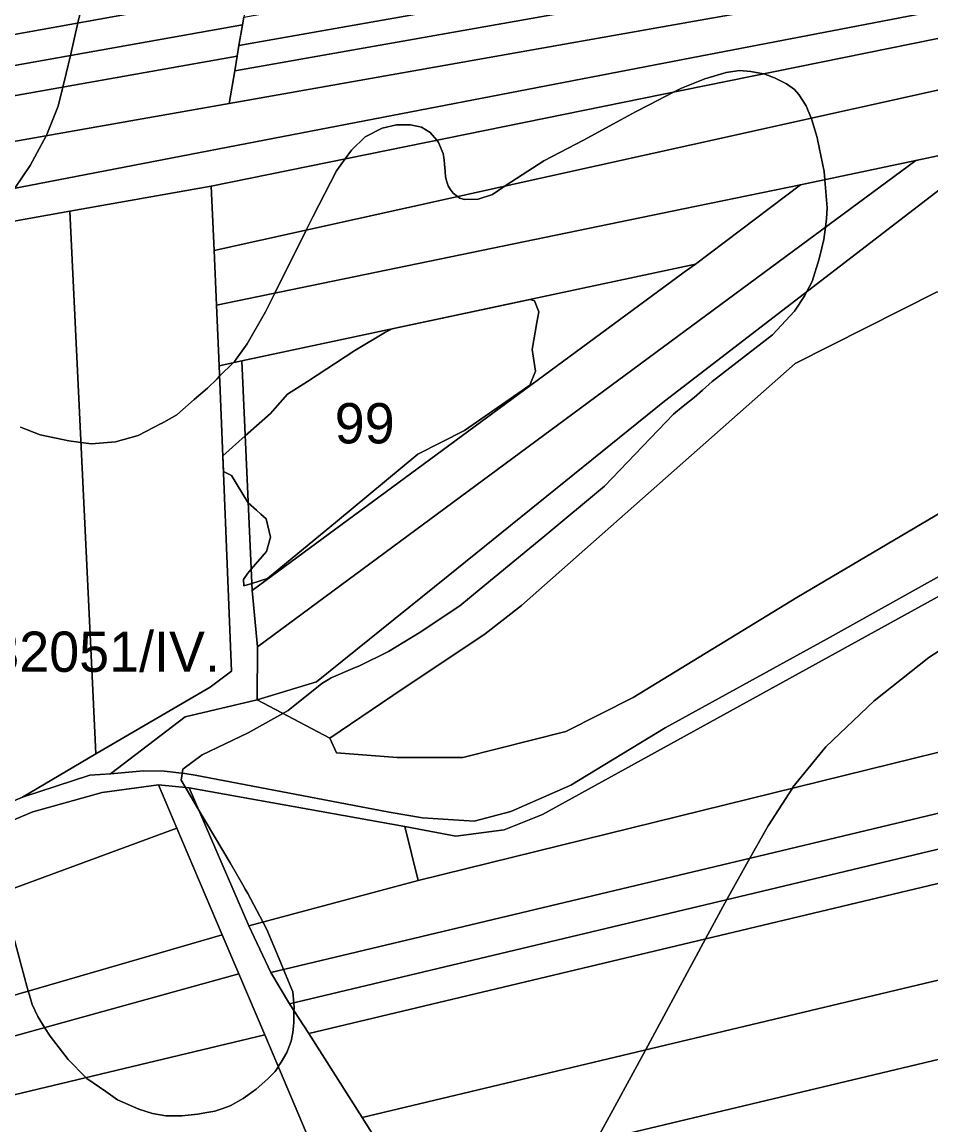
# Model space of a CAD drawing. Extents: x -521939 to -516426, y -1197857 to -1189551.
# Drawn here: x -521390.7 to -521052.2, y -1191196.8 to -1190786 of the extents above; entities that cross this region are included whole.
import ezdxf

# ---------------------------------------------------------------- set-up
doc = ezdxf.new("R2010")
doc.units = 0
for name, color, linetype in [('95560013', 7, 'Continuous'), ('95610013', 7, 'Continuous'), ('95630013', 7, 'Continuous'), ('95640013', 7, 'Continuous'), ('95660013', 7, 'Continuous')]:
    doc.layers.add(name, color=color, linetype=linetype)

msp = doc.modelspace()

# ---------------------------------------------------------------- linework, layer by layer
at = {"layer": '95560013'}
for points in [[(-521290.17, -1190674.88), (-521293.24, -1190693.91), (-521296.33, -1190712.88), (-521297.51, -1190719.97), (-521298.87, -1190728.16), (-521300.83, -1190740.08), (-521302.74, -1190751.74), (-521304.64, -1190763.28), (-521306.54, -1190774.85), (-521450.36, -1190800.76), (-521627.54, -1190832.68), (-521603.17, -1190799.85), (-521437.14, -1190733.56)], [(-521308.13, -1190784.21), (-521129.72, -1190752.09), (-520951.31, -1190719.97), (-520853.44, -1190702.35), (-520853.63, -1190713.88), (-520965.54, -1190733.72), (-521143.84, -1190765.33), (-521309.9, -1190794.77), (-521308.62, -1190787.06)], [(-521310.55, -1190798.66), (-521309.9, -1190794.77), (-521143.84, -1190765.33), (-520965.54, -1190733.72), (-520853.63, -1190713.88), (-520853.79, -1190723.11), (-520956.84, -1190741.35), (-521130.85, -1190772.15), (-521311.47, -1190804.12)], [(-520853.79, -1190723.11), (-520853.87, -1190735.1), (-520958.48, -1190753.58), (-521136, -1190784.94), (-521313.52, -1190816.3), (-521311.47, -1190804.12), (-521130.85, -1190772.15), (-520956.84, -1190741.35)], [(-521313.52, -1190816.3), (-521136, -1190784.94), (-520958.48, -1190753.58), (-520853.87, -1190735.1), (-520853.81, -1190743.83), (-520959.05, -1190764.12), (-521138.15, -1190798.65), (-521317.25, -1190833.18), (-521501.29, -1190868.66), (-521677.29, -1190902.59), (-521660.16, -1190877.52), (-521482.65, -1190846.17)], [(-521681.39, -1190911.18), (-521677.29, -1190902.59), (-521501.29, -1190868.66), (-521317.25, -1190833.18), (-521138.15, -1190798.65), (-520959.05, -1190764.12), (-520853.81, -1190743.83), (-520853.6, -1190752.22), (-520963.96, -1190774.66), (-521145.09, -1190811.49), (-521320.22, -1190847.1), (-521372.85, -1190856.47), (-521425.01, -1190865.8), (-521453.93, -1190870.89), (-521460.01, -1190871.96), (-521483.31, -1190876.02), (-521504.24, -1190879.82), (-521526.13, -1190883.61), (-521548.65, -1190887.54)], [(-520853.6, -1190752.22), (-520853.48, -1190767.88), (-520962.56, -1190792.05), (-521140.87, -1190831.56), (-521319.18, -1190871.07), (-521320.22, -1190847.1), (-521145.09, -1190811.49), (-520963.96, -1190774.66)], [(-521636.8, -1190845.39), (-521627.54, -1190832.68), (-521450.36, -1190800.76), (-521306.54, -1190774.85), (-521306.91, -1190777.02), (-521308.13, -1190784.21), (-521308.62, -1190787.06), (-521459.01, -1190813.79)], [(-521308.62, -1190787.06), (-521309.9, -1190794.77), (-521310.55, -1190798.66), (-521470.11, -1190827.02), (-521646.38, -1190858.35), (-521636.8, -1190845.39), (-521459.01, -1190813.79)], [(-521646.38, -1190858.35), (-521470.11, -1190827.02), (-521310.55, -1190798.66), (-521311.47, -1190804.12), (-521313.52, -1190816.3), (-521482.65, -1190846.17), (-521660.16, -1190877.52)], [(-521204.73, -1191003.3), (-521102.75, -1190913.16), (-521050.15, -1190886.58), (-521012.31, -1190879.41), (-520849.49, -1190848.58), (-520847.98, -1190871.46), (-520845.07, -1190897.78), (-520896.6, -1190901.88), (-520958.97, -1190920.92), (-521001.86, -1190941.06), (-521102.12, -1191000.34), (-521163.1, -1191037.51), (-521188.22, -1191050.28), (-521226.57, -1191059.93), (-521251.03, -1191059.96), (-521273.53, -1191058.18), (-521276.05, -1191052.73), (-521252.59, -1191036.79), (-521218.27, -1191013.84)], [(-521248.14, -1191085.64), (-521229.14, -1191089.2), (-521211.09, -1191086.92), (-521196.9, -1191081.18), (-521042.5, -1190996.08), (-520867.54, -1190954.4), (-520838.45, -1190947.47), (-520829.51, -1191003.76), (-520890.59, -1191018.81), (-521066.89, -1191062.25), (-521243.19, -1191105.69)], [(-520829.51, -1191003.76), (-520825.08, -1191027.11), (-520948.1, -1191056.48), (-521121.97, -1191097.99), (-521298.06, -1191140.03), (-521306.22, -1191122.56), (-521243.19, -1191105.69), (-521066.89, -1191062.25), (-520890.59, -1191018.81)], [(-520825.08, -1191027.11), (-520822.58, -1191039.85), (-520945.68, -1191069.25), (-521118.02, -1191110.41), (-521291.03, -1191151.73), (-521298.06, -1191140.03), (-521121.97, -1191097.99), (-520948.1, -1191056.48)], [(-520945.68, -1191069.25), (-520822.58, -1191039.85), (-520820.01, -1191052.05), (-520940.27, -1191080.75), (-521112.07, -1191121.75), (-521283.87, -1191162.75), (-521291.03, -1191151.73), (-521118.02, -1191110.41)], [(-520820.01, -1191052.05), (-520812.23, -1191086.24), (-520915.1, -1191110.79), (-521089.12, -1191152.32), (-521264.02, -1191194.06), (-521283.87, -1191162.75), (-521112.07, -1191121.75), (-520940.27, -1191080.75)], [(-521339.87, -1191070.1), (-521333.03, -1191086.18), (-521492.1, -1191144.87), (-521665.86, -1191208.98), (-521668.23, -1191202.31), (-521666.02, -1191197.62), (-521498.24, -1191127.07), (-521386.68, -1191080.16), (-521360.86, -1191072.9)], [(-521243.19, -1191105.69), (-521306.22, -1191122.56), (-521328.5, -1191071.27), (-521248.14, -1191085.64)], [(-521333.03, -1191086.18), (-521316.14, -1191125.96), (-521487.7, -1191175.74), (-521659.26, -1191225.52), (-521665.86, -1191208.98), (-521492.1, -1191144.87)], [(-520812.23, -1191086.24), (-520805.2, -1191114.16), (-520903.8, -1191137.67), (-521078.73, -1191179.38), (-521253.66, -1191221.09), (-521257.44, -1191204.41), (-521264.02, -1191194.06), (-521089.12, -1191152.32), (-520915.1, -1191110.79)], [(-520805.2, -1191114.16), (-520797.61, -1191144.17), (-520897.63, -1191168.05), (-521072.33, -1191209.76), (-521247.03, -1191251.47), (-521253.66, -1191221.09), (-521078.73, -1191179.38), (-520903.8, -1191137.67)], [(-521659.26, -1191225.52), (-521487.7, -1191175.74), (-521316.14, -1191125.96), (-521309.96, -1191140.46), (-521476.8, -1191186.64), (-521654.37, -1191235.79)], [(-521300.29, -1191163.2), (-521649.4, -1191246.83), (-521654.37, -1191235.79), (-521476.8, -1191186.64), (-521309.96, -1191140.46)], [(-521632.86, -1191283.41), (-521649.4, -1191246.83), (-521300.29, -1191163.2), (-521277.99, -1191215.69), (-521624.98, -1191298.54)]]:
    msp.add_lwpolyline(points, close=True, dxfattribs=at)
at = {"layer": '95610013'}
for points in [[(-520853.48, -1190767.88), (-520852.66, -1190794.34), (-520930.46, -1190808.82), (-521026.22, -1190830.89), (-521057.89, -1190837.57), (-521100.8, -1190846.62), (-521144.36, -1190855.59), (-521318.26, -1190891.4), (-521319.18, -1190871.07), (-521140.87, -1190831.56), (-520962.56, -1190792.05)], [(-521303.06, -1191018.65), (-521157.58, -1190911.2), (-521057.89, -1190837.57), (-521026.22, -1190830.89), (-521151.49, -1190927.2), (-521231.97, -1190992.2), (-521281.09, -1191031.69), (-521303.14, -1191038.45)], [(-521100.8, -1190846.62), (-521057.89, -1190837.57), (-521157.58, -1190911.2), (-521303.06, -1191018.65), (-521304.95, -1190997.73), (-521144.09, -1190879.2), (-521139.91, -1190876.12)], [(-521317.26, -1190913.98), (-521312.68, -1191027.8), (-521320.66, -1191033.71), (-521363.22, -1191058.53), (-521364.35, -1191034.82), (-521372.85, -1190856.47), (-521320.22, -1190847.1), (-521319.18, -1190871.07), (-521318.26, -1190891.4)], [(-521318.26, -1190891.4), (-521144.36, -1190855.59), (-521100.8, -1190846.62), (-521139.91, -1190876.12), (-521308.8, -1190912.17), (-521317.26, -1190913.98)], [(-521372.85, -1190856.47), (-521364.35, -1191034.82), (-521363.22, -1191058.53), (-521390.55, -1191074.73), (-521409.4, -1191082.63), (-521412.23, -1191043.32), (-521425.01, -1190865.8)]]:
    msp.add_lwpolyline(points, close=True, dxfattribs=at)
at = {"layer": '95630013'}
msp.add_lwpolyline([(-521004.39, -1190967.44), (-521090.82, -1191015.73), (-521151.15, -1191048.86), (-521186.27, -1191070.2), (-521208.62, -1191080.01), (-521222.3, -1191083.69), (-521241.52, -1191082.44), (-521254, -1191080.26), (-521326.25, -1191066.55), (-521330.04, -1191065.83), (-521337.72, -1191065.02), (-521345.44, -1191064.87), (-521357.75, -1191066.04), (-521329.97, -1191044.74), (-521303.14, -1191038.45), (-521276.05, -1191052.73), (-521273.53, -1191058.18), (-521251.03, -1191059.96), (-521226.57, -1191059.93), (-521188.22, -1191050.28), (-521163.1, -1191037.51), (-521102.12, -1191000.34), (-521001.86, -1190941.06)], dxfattribs=at)
at = {"layer": '95640013'}
for points in [[(-520930.46, -1190808.82), (-520955.91, -1190827.93), (-521012.31, -1190879.41), (-521050.15, -1190886.58), (-521102.75, -1190913.16), (-521204.73, -1191003.3), (-521218.27, -1191013.84), (-521252.59, -1191036.79), (-521276.05, -1191052.73), (-521303.14, -1191038.45), (-521281.09, -1191031.69), (-521231.97, -1190992.2), (-521151.49, -1190927.2), (-521026.22, -1190830.89)], [(-521139.91, -1190876.12), (-521144.09, -1190879.2), (-521304.95, -1190997.73), (-521308.8, -1190912.17)], [(-521308.8, -1190912.17), (-521304.95, -1190997.73), (-521303.06, -1191018.65), (-521303.14, -1191038.45), (-521329.97, -1191044.74), (-521357.75, -1191066.04), (-521365.39, -1191066.49), (-521390.55, -1191074.73), (-521363.22, -1191058.53), (-521320.66, -1191033.71), (-521312.68, -1191027.8), (-521317.26, -1190913.98)]]:
    msp.add_lwpolyline(points, close=True, dxfattribs=at)
for points in [[(-521409.4, -1191082.63), (-521390.55, -1191074.73), (-521365.39, -1191066.49), (-521357.75, -1191066.04), (-521345.44, -1191064.87), (-521337.72, -1191065.02), (-521330.04, -1191065.83), (-521326.25, -1191066.55), (-521254, -1191080.26), (-521241.52, -1191082.44), (-521222.3, -1191083.69), (-521208.62, -1191080.01), (-521186.27, -1191070.2), (-521151.15, -1191048.86), (-521090.82, -1191015.73), (-521004.39, -1190967.44)], [(-521042.5, -1190996.08), (-521196.9, -1191081.18), (-521211.09, -1191086.92), (-521229.14, -1191089.2), (-521248.14, -1191085.64), (-521328.5, -1191071.27), (-521339.87, -1191070.1), (-521360.86, -1191072.9), (-521386.68, -1191080.16), (-521498.24, -1191127.07)], [(-521277.99, -1191215.69), (-521300.29, -1191163.2), (-521309.96, -1191140.46), (-521316.14, -1191125.96), (-521333.03, -1191086.18), (-521339.87, -1191070.1), (-521328.5, -1191071.27), (-521306.22, -1191122.56), (-521298.06, -1191140.03), (-521291.03, -1191151.73), (-521283.87, -1191162.75), (-521264.02, -1191194.06), (-521257.44, -1191204.41)]]:
    msp.add_lwpolyline(points, dxfattribs=at)
at = {"layer": '95660013'}
for points in [[(-521367.46, -1190775.97), (-521369.85, -1190786.26), (-521372.69, -1190798.45), (-521374.23, -1190805.09), (-521375.49, -1190810.2), (-521377.25, -1190817.38), (-521381.42, -1190827.81), (-521381.71, -1190828.34), (-521387.68, -1190839.4), (-521393.37, -1190847.86)], [(-521393.37, -1190847.86), (-521387.68, -1190839.4), (-521381.71, -1190828.34), (-521381.42, -1190827.81), (-521377.25, -1190817.38), (-521375.49, -1190810.2), (-521374.23, -1190805.09), (-521372.69, -1190798.45), (-521369.85, -1190786.26), (-521367.46, -1190775.97)], [(-521391.27, -1190936.88), (-521383.97, -1190939.78), (-521373.31, -1190941.98), (-521369.6, -1190942.44), (-521368.75, -1190942.55), (-521364.84, -1190943.03), (-521355.92, -1190942.33), (-521347.46, -1190940.01), (-521338.91, -1190935.57), (-521338.76, -1190935.49), (-521333.08, -1190932.25), (-521326.54, -1190926.63), (-521321.61, -1190922.39), (-521318, -1190918.82), (-521317.1, -1190917.93), (-521311.94, -1190912.84), (-521311.52, -1190912.43), (-521306.89, -1190905.82), (-521300.05, -1190893.88), (-521296.59, -1190886.94), (-521284.89, -1190863.47), (-521282.43, -1190858.53), (-521273.59, -1190841.43), (-521270.33, -1190836.96), (-521267.99, -1190833.74), (-521262.85, -1190828.72), (-521256.56, -1190825.57), (-521251.19, -1190824.29), (-521246.06, -1190824.29), (-521241.98, -1190825.11), (-521238.71, -1190827.09), (-521236.23, -1190830.03), (-521235.56, -1190830.82), (-521233.81, -1190834.9), (-521233.63, -1190836.47), (-521233.52, -1190837.38), (-521233.34, -1190838.87), (-521233.15, -1190841.53), (-521233, -1190843.65), (-521232.49, -1190845.49), (-521232.06, -1190847.03), (-521231.24, -1190848.21), (-521230.2, -1190849.72), (-521228.47, -1190850.97), (-521227.63, -1190851.58), (-521226.41, -1190851.93), (-521226, -1190852.05), (-521220.86, -1190851.93), (-521215.5, -1190850.18), (-521210.77, -1190847.05), (-521206.52, -1190844.23), (-521196.37, -1190837.7), (-521181.56, -1190830), (-521167.74, -1190822.45), (-521162.25, -1190819.45), (-521157.19, -1190816.82), (-521148.1, -1190812.1), (-521145.17, -1190810.58), (-521136.48, -1190807.08), (-521128.49, -1190804.75), (-521123.53, -1190804.05), (-521119.33, -1190804.4), (-521114.63, -1190805.3), (-521114.14, -1190805.39), (-521110.46, -1190806.73), (-521105.97, -1190809.01), (-521103.06, -1190811.05), (-521101.48, -1190812.97), (-521098.74, -1190817.17), (-521096.81, -1190821.8), (-521096.58, -1190822.36), (-521094.64, -1190829.03), (-521094.43, -1190829.77), (-521092.04, -1190841.61), (-521091.77, -1190844.72), (-521090.87, -1190855.2), (-521091.1, -1190859.28), (-521091.53, -1190862.41), (-521092.15, -1190866.98), (-521092.86, -1190870.11), (-521093.79, -1190874.21), (-521096.47, -1190882.61), (-521098.39, -1190886.38), (-521099.15, -1190887.86), (-521103, -1190893.69), (-521111.28, -1190902.44), (-521133.68, -1190919.93), (-521137.3, -1190923.05), (-521140.44, -1190925.77), (-521144.52, -1190929.1), (-521148.14, -1190932.06), (-521173.8, -1190958.89), (-521195.96, -1190977.32), (-521220.49, -1190997.52), (-521227.69, -1191003.45), (-521242.85, -1191013.48), (-521254.28, -1191020.48), (-521265.25, -1191025.84), (-521266.63, -1191026.44), (-521275.51, -1191030.28), (-521277.19, -1191031.28), (-521279.01, -1191032.37), (-521291.54, -1191042.36), (-521306.46, -1191050.69), (-521323.6, -1191058.95), (-521330.8, -1191064.24), (-521331.41, -1191068.41), (-521329.79, -1191071.14), (-521327.43, -1191075.12), (-521325.19, -1191078.89), (-521313.15, -1191099.16), (-521308.44, -1191107.39), (-521307.58, -1191108.9), (-521306.66, -1191110.52), (-521300.97, -1191121.15), (-521299.47, -1191123.96), (-521294.37, -1191136.37), (-521293.32, -1191138.9), (-521289.85, -1191147.26), (-521289.53, -1191151.37), (-521289.39, -1191153.17), (-521289.41, -1191154.22), (-521289.5, -1191158.74), (-521289.85, -1191162.33), (-521290.43, -1191165.58), (-521292.05, -1191169.75), (-521294.14, -1191173.46), (-521295.25, -1191175.07), (-521295.46, -1191175.38), (-521296.46, -1191176.82), (-521299.12, -1191179.6), (-521303.53, -1191183.43), (-521308.39, -1191186.9), (-521313.15, -1191189.68), (-521316.22, -1191190.73), (-521318.94, -1191191.66), (-521321.87, -1191192.19), (-521325.32, -1191192.81), (-521331.23, -1191193.39), (-521337.14, -1191193.39), (-521342.13, -1191192.58), (-521347.23, -1191190.96), (-521355.11, -1191187.37), (-521359.5, -1191184.35), (-521366.58, -1191179.48), (-521366.9, -1191179.16), (-521373.54, -1191172.41), (-521380.26, -1191163.72), (-521382.27, -1191160.47), (-521384.78, -1191156.42), (-521386.87, -1191151.9), (-521387.91, -1191148.47), (-521388.14, -1191147.73), (-521388.36, -1191146.92), (-521393.47, -1191127.9)], [(-521393.47, -1191127.9), (-521388.36, -1191146.92), (-521388.14, -1191147.73), (-521387.91, -1191148.47), (-521386.87, -1191151.9), (-521384.78, -1191156.42), (-521382.27, -1191160.47), (-521380.26, -1191163.72), (-521373.54, -1191172.41), (-521366.9, -1191179.16), (-521366.58, -1191179.48), (-521359.5, -1191184.35), (-521355.11, -1191187.37), (-521347.23, -1191190.96), (-521342.13, -1191192.58), (-521337.14, -1191193.39), (-521331.23, -1191193.39), (-521325.32, -1191192.81), (-521321.87, -1191192.19), (-521318.94, -1191191.66), (-521316.22, -1191190.73), (-521313.15, -1191189.68), (-521308.39, -1191186.9), (-521303.53, -1191183.43), (-521299.12, -1191179.6), (-521296.46, -1191176.82), (-521295.46, -1191175.38), (-521295.25, -1191175.07), (-521294.14, -1191173.46), (-521292.05, -1191169.75), (-521290.43, -1191165.58), (-521289.85, -1191162.33), (-521289.5, -1191158.74), (-521289.41, -1191154.22), (-521289.39, -1191153.17), (-521289.53, -1191151.37), (-521289.85, -1191147.26), (-521293.32, -1191138.9), (-521294.37, -1191136.37), (-521299.47, -1191123.96), (-521300.97, -1191121.15), (-521306.66, -1191110.52), (-521307.58, -1191108.9), (-521308.44, -1191107.39), (-521313.15, -1191099.16), (-521325.19, -1191078.89), (-521327.43, -1191075.12), (-521329.79, -1191071.14), (-521331.41, -1191068.41), (-521330.8, -1191064.24), (-521323.6, -1191058.95), (-521306.46, -1191050.69), (-521291.54, -1191042.36), (-521279.01, -1191032.37), (-521277.19, -1191031.28), (-521275.51, -1191030.28), (-521266.63, -1191026.44), (-521265.25, -1191025.84), (-521254.28, -1191020.48), (-521242.85, -1191013.48), (-521227.69, -1191003.45), (-521220.49, -1190997.52), (-521195.96, -1190977.32), (-521173.8, -1190958.89), (-521148.14, -1190932.06), (-521144.52, -1190929.1), (-521140.44, -1190925.77), (-521137.3, -1190923.05), (-521133.68, -1190919.93), (-521111.28, -1190902.44), (-521103, -1190893.69), (-521099.15, -1190887.86), (-521098.39, -1190886.38), (-521096.47, -1190882.61), (-521093.79, -1190874.21), (-521092.86, -1190870.11), (-521092.15, -1190866.98), (-521091.53, -1190862.41), (-521091.1, -1190859.28), (-521090.87, -1190855.2), (-521091.77, -1190844.72), (-521092.04, -1190841.61), (-521094.43, -1190829.77), (-521094.64, -1190829.03), (-521096.58, -1190822.36), (-521096.81, -1190821.8), (-521098.74, -1190817.17), (-521101.48, -1190812.97), (-521103.06, -1190811.05), (-521105.97, -1190809.01), (-521110.46, -1190806.73), (-521114.14, -1190805.39), (-521114.63, -1190805.3), (-521119.33, -1190804.4), (-521123.53, -1190804.05), (-521128.49, -1190804.75), (-521136.48, -1190807.08), (-521145.17, -1190810.58), (-521148.1, -1190812.1), (-521157.19, -1190816.82), (-521162.25, -1190819.45), (-521167.74, -1190822.45), (-521181.56, -1190830), (-521196.37, -1190837.7), (-521206.52, -1190844.23), (-521210.77, -1190847.05), (-521215.5, -1190850.18), (-521220.86, -1190851.93), (-521226, -1190852.05), (-521226.41, -1190851.93), (-521227.63, -1190851.58), (-521228.47, -1190850.97), (-521230.2, -1190849.72), (-521231.24, -1190848.21), (-521232.06, -1190847.03), (-521232.49, -1190845.49), (-521233, -1190843.65), (-521233.15, -1190841.53), (-521233.34, -1190838.87), (-521233.52, -1190837.38), (-521233.63, -1190836.47), (-521233.81, -1190834.9), (-521235.56, -1190830.82), (-521236.23, -1190830.03), (-521238.71, -1190827.09), (-521241.98, -1190825.11), (-521246.06, -1190824.29), (-521251.19, -1190824.29), (-521256.56, -1190825.57), (-521262.85, -1190828.72), (-521267.99, -1190833.74), (-521270.33, -1190836.96), (-521273.59, -1190841.43), (-521282.43, -1190858.53), (-521284.89, -1190863.47), (-521296.59, -1190886.94), (-521300.05, -1190893.88), (-521306.89, -1190905.82), (-521311.52, -1190912.43), (-521311.94, -1190912.84), (-521317.1, -1190917.93), (-521318, -1190918.82), (-521321.61, -1190922.39), (-521326.54, -1190926.63), (-521333.08, -1190932.25), (-521338.76, -1190935.49), (-521338.91, -1190935.57), (-521347.46, -1190940.01), (-521355.92, -1190942.33), (-521364.84, -1190943.03), (-521368.75, -1190942.55), (-521369.6, -1190942.44), (-521373.31, -1190941.98), (-521383.97, -1190939.78), (-521391.27, -1190936.88)], [(-521177.05, -1191202.82), (-521169.92, -1191189.94), (-521158.56, -1191168.89), (-521136.23, -1191127.52), (-521130.51, -1191116.91), (-521128.24, -1191112.85), (-521119.63, -1191097.43), (-521112.9, -1191085.39), (-521103.84, -1191071.36), (-521103.62, -1191071.01), (-521091.34, -1191055.95), (-521073.43, -1191038.85), (-521053.03, -1191022.62), (-521027.06, -1191005.93)], [(-521027.06, -1191005.93), (-521053.03, -1191022.62), (-521073.43, -1191038.85), (-521091.34, -1191055.95), (-521103.62, -1191071.01), (-521103.84, -1191071.36), (-521112.9, -1191085.39), (-521119.63, -1191097.43), (-521128.24, -1191112.85), (-521130.51, -1191116.91), (-521136.23, -1191127.52), (-521158.56, -1191168.89), (-521169.92, -1191189.94), (-521177.05, -1191202.82)]]:
    msp.add_lwpolyline(points, dxfattribs=at)
for points in [[(-521307.54, -1190940.09), (-521315.91, -1190947.52), (-521315.67, -1190953.41), (-521312.63, -1190954.93), (-521306.74, -1190964.73), (-521306.42, -1190965.02), (-521303.41, -1190967.78), (-521301.8, -1190969.23), (-521299.74, -1190971.08), (-521298.2, -1190977.88), (-521299.69, -1190983.25), (-521305.31, -1190989.76), (-521306.61, -1190991.26), (-521308.24, -1190993.58), (-521308.03, -1190996.04), (-521305.07, -1190995.11), (-521299.22, -1190993.28), (-521273.26, -1190971.73), (-521243.32, -1190946.9), (-521225.92, -1190938.09), (-521201.62, -1190921.26), (-521199.48, -1190916.06), (-521200.77, -1190907.93), (-521199, -1190897.86), (-521198.26, -1190893.95), (-521199.82, -1190889.86), (-521201.52, -1190889.27), (-521252.82, -1190900.22), (-521255.39, -1190901.52), (-521266.74, -1190908.33), (-521284.43, -1190919.82), (-521291.85, -1190924.56), (-521296.44, -1190929.79), (-521298.16, -1190931.75)], [(-521305.07, -1190995.11), (-521308.03, -1190996.04), (-521308.24, -1190993.58), (-521306.61, -1190991.26), (-521305.31, -1190989.76), (-521299.69, -1190983.25), (-521298.2, -1190977.88), (-521299.74, -1190971.08), (-521301.8, -1190969.23), (-521303.41, -1190967.78), (-521306.42, -1190965.02), (-521306.74, -1190964.73), (-521312.63, -1190954.93), (-521315.67, -1190953.41), (-521315.91, -1190947.52), (-521307.54, -1190940.09), (-521298.16, -1190931.75), (-521296.44, -1190929.79), (-521291.85, -1190924.56), (-521284.43, -1190919.82), (-521266.74, -1190908.33), (-521255.39, -1190901.52), (-521252.82, -1190900.22), (-521201.52, -1190889.27), (-521199.82, -1190889.86), (-521198.26, -1190893.95), (-521199, -1190897.86), (-521200.77, -1190907.93), (-521199.48, -1190916.06), (-521201.62, -1190921.26), (-521225.92, -1190938.09), (-521243.32, -1190946.9), (-521273.26, -1190971.73), (-521299.22, -1190993.28)]]:
    msp.add_lwpolyline(points, close=True, dxfattribs=at)

# ---------------------------------------------------------------- texts
for s, rotation, p in [('99', 0, (-521274.24, -1190942.92)), ('32051/IV.', 360, (-521402.87, -1191028.01))]:
    msp.add_text(s, height=15, rotation=rotation, dxfattribs=at).set_placement(p)

doc.saveas('drawing.dxf')
